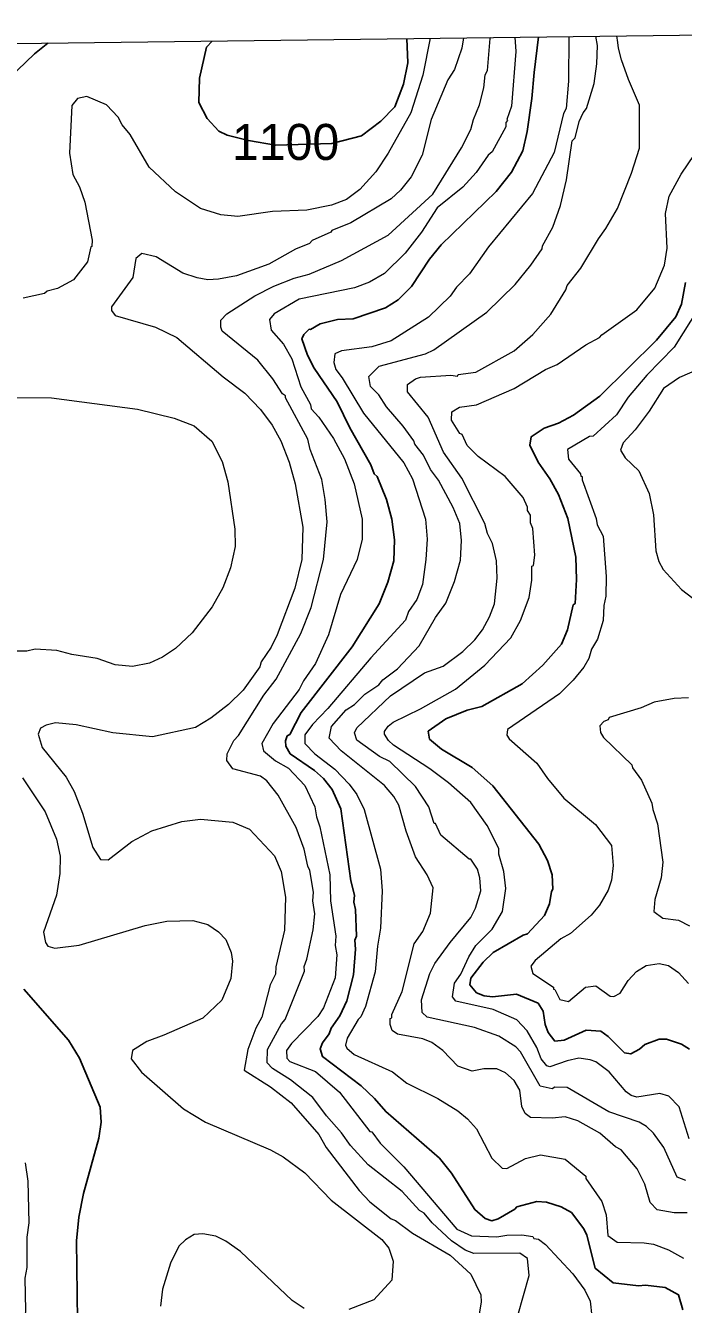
# Model space of a CAD drawing. Extents: x 265.7 to 292.1, y 7676.2 to 7704.2.
# Drawn here: x 288.593 to 290.054, y 7701.364 to 7704.203 of the extents above; entities that cross this region are included whole.
import ezdxf
from ezdxf.enums import TextEntityAlignment as Align

# ---------------------------------------------------------------- set-up
doc = ezdxf.new("R2010")
doc.units = 0
doc.header["$LTSCALE"] = 0.032
for name, color, linetype, lineweight in [('1', 7, 'Continuous', 25), ('2', 7, 'Continuous', 13), ('63', 7, 'Continuous', 25)]:
    doc.layers.add(name, color=color, linetype=linetype, lineweight=lineweight)
doc.layers.add('61', color=7, linetype='Continuous')

msp = doc.modelspace()

# ---------------------------------------------------------------- linework, layer by layer
at = {"layer": '1'}
for points in [[(288.6424, 7704.1641), (288.6129, 7704.1406), (288.5565, 7704.0866)], [(289.4399, 7704.1741), (289.4423, 7704.1205), (289.4325, 7704.0726), (289.4129, 7704.0224), (289.3823, 7703.9905), (289.3394, 7703.9586), (289.2733, 7703.9415), (289.1483, 7703.9378), (289.0883, 7703.9476), (289.0405, 7703.9599), (289.0222, 7703.9684), (288.9964, 7703.9966), (288.978, 7704.0322), (288.9793, 7704.0862), (288.9952, 7704.1548), (289.0076, 7704.1687)], [(289.293, 7702.4643), (289.2739, 7702.5074), (289.2547, 7702.5313), (289.2348, 7702.5497), (289.1805, 7702.5864), (289.171, 7702.6032), (289.1702, 7702.6151), (289.1741, 7702.6263), (289.1797, 7702.6295), (289.2053, 7702.6782), (289.3186, 7702.8242), (289.3784, 7702.9192), (289.3976, 7702.9671), (289.4111, 7703.0149), (289.4127, 7703.0612), (289.4064, 7703.1075), (289.3944, 7703.1506), (289.3736, 7703.2017), (289.3673, 7703.208), (289.3601, 7703.228), (289.313, 7703.3102), (289.2851, 7703.3676), (289.234, 7703.4426), (289.2188, 7703.4714), (289.2069, 7703.5073), (289.2108, 7703.5176), (289.2228, 7703.5288), (289.226, 7703.528), (289.2476, 7703.5408), (289.2859, 7703.5503), (289.3202, 7703.5519), (289.392, 7703.5767), (289.4207, 7703.5942), (289.4502, 7703.6238), (289.4901, 7703.6844), (289.5157, 7703.7163), (289.6378, 7703.8344), (289.6721, 7703.8775), (289.6976, 7703.9246), (289.7072, 7703.9677), (289.7173, 7704.0413), (289.7224, 7704.0986), (289.7319, 7704.1777)], [(290.0583, 7703.6326), (290.0495, 7703.5847), (290.0367, 7703.5567), (289.9944, 7703.5049), (289.8684, 7703.3804), (289.8101, 7703.3381), (289.7766, 7703.3205), (289.7447, 7703.3094), (289.716, 7703.2902), (289.7128, 7703.2719), (289.7311, 7703.2336), (289.7575, 7703.1969), (289.7766, 7703.1618), (289.7974, 7703.1091), (289.8149, 7703.0229), (289.8165, 7702.9734), (289.8133, 7702.92), (289.8093, 7702.9168), (289.7966, 7702.8617), (289.783, 7702.8298), (289.7415, 7702.7835), (289.696, 7702.742), (289.6059, 7702.6917), (289.5739, 7702.683), (289.5261, 7702.6638), (289.4869, 7702.6367)], [(289.4869, 7702.6367), (289.4901, 7702.6191), (289.5165, 7702.5968), (289.5851, 7702.5561), (289.6306, 7702.5154), (289.7327, 7702.3861), (289.7519, 7702.3494)], [(289.3242, 7702.1731), (289.3282, 7702.1819), (289.3258, 7702.2409), (289.3218, 7702.2569), (289.3234, 7702.2728), (289.3154, 7702.3047), (289.293, 7702.4643)], [(289.7519, 7702.3494), (289.7622, 7702.3175), (289.7638, 7702.2856), (289.7606, 7702.2808), (289.7567, 7702.2537), (289.7455, 7702.2273), (289.708, 7702.1866), (289.6984, 7702.1842), (289.6314, 7702.1451), (289.609, 7702.1236), (289.5819, 7702.0885), (289.5795, 7702.0733), (289.5947, 7702.0558), (289.6114, 7702.0494), (289.6298, 7702.047), (289.6832, 7702.0526), (289.7311, 7702.0326), (289.7423, 7702.0151), (289.7471, 7701.9856), (289.7535, 7701.968), (289.7686, 7701.9488), (289.7894, 7701.9504), (289.838, 7701.9728), (289.8708, 7701.9704), (289.8867, 7701.9592), (289.9234, 7701.9225), (289.937, 7701.9201), (289.9562, 7701.9305), (289.9681, 7701.9409), (290, 7701.9528), (290.016, 7701.9528), (290.0495, 7701.9417), (290.0671, 7701.9305)], [(290.0527, 7701.352), (290.0431, 7701.3855), (290.0136, 7701.4014), (289.9697, 7701.407), (289.9538, 7701.4054), (289.8979, 7701.4118), (289.858, 7701.4445), (289.8396, 7701.518), (289.8325, 7701.5323), (289.8053, 7701.5682), (289.7822, 7701.581), (289.7495, 7701.5913), (289.7287, 7701.5929), (289.6841, 7701.581), (289.6793, 7701.5754), (289.6426, 7701.5538), (289.6282, 7701.5499), (289.6138, 7701.5546), (289.5907, 7701.5746), (289.5388, 7701.6552), (289.5125, 7701.6887), (289.3928, 7701.7924), (289.3681, 7701.8212), (289.3385, 7701.8491), (289.2523, 7701.9145), (289.2476, 7701.9313), (289.2523, 7701.9449), (289.2675, 7701.9648), (289.2715, 7701.9776), (289.2906, 7702.0047), (289.3066, 7702.0382), (289.321, 7702.0957), (289.3258, 7702.1531), (289.3242, 7702.1731)], [(288.5892, 7702.0638), (288.6882, 7701.9504), (288.7129, 7701.9105), (288.7584, 7701.802), (288.7608, 7701.7685), (288.756, 7701.7334), (288.7217, 7701.6105), (288.7113, 7701.5579), (288.7065, 7701.5052), (288.7081, 7701.328), (288.7281, 7701.0599), (288.7361, 7701.0232), (288.752, 7700.9083), (288.7504, 7700.7982), (288.7353, 7700.728), (288.7081, 7700.6705), (288.6834, 7700.6322), (288.6044, 7700.5556), (288.5757, 7700.5205)]]:
    msp.add_lwpolyline(points, dxfattribs=at)
at = {"layer": '2'}
for points in [[(289.4914, 7704.1747), (289.4754, 7704.0931), (289.4483, 7704.0091), (289.3984, 7703.9198), (289.3712, 7703.8783), (289.3353, 7703.8392), (289.3058, 7703.8169), (289.2723, 7703.8041), (289.218, 7703.7929), (289.1414, 7703.7905), (289.0648, 7703.7794), (289.0265, 7703.7826), (288.9818, 7703.7969), (288.926, 7703.8336), (288.8677, 7703.8887), (288.8254, 7703.9613), (288.8079, 7703.9828), (288.7991, 7703.9996), (288.7728, 7704.0267), (288.7289, 7704.0459), (288.7081, 7704.0411), (288.6962, 7704.0259), (288.6906, 7703.9198), (288.6978, 7703.8727), (288.7129, 7703.8448), (288.7249, 7703.8113), (288.7409, 7703.7267), (288.7401, 7703.7123), (288.7377, 7703.7115), (288.7305, 7703.6788), (288.6994, 7703.6389), (288.6643, 7703.619), (288.6411, 7703.6134), (288.6355, 7703.6086), (288.5877, 7703.5982)], [(289.5654, 7704.1756), (289.5617, 7704.1531), (289.5452, 7704.1057), (289.5308, 7704.0826), (289.4941, 7703.9948), (289.4734, 7703.915), (289.4494, 7703.8672), (289.4255, 7703.8376), (289.4048, 7703.8185), (289.3154, 7703.765), (289.2731, 7703.7482), (289.2707, 7703.7443), (289.2292, 7703.7259), (289.2236, 7703.7195), (289.1925, 7703.7068), (289.1335, 7703.6732), (289.0616, 7703.6477), (289.0217, 7703.6397), (288.9978, 7703.6389), (288.9739, 7703.6429), (288.942, 7703.6533), (288.8829, 7703.69), (288.851, 7703.6972), (288.8382, 7703.686), (288.831, 7703.6437), (288.7839, 7703.5783), (288.7839, 7703.5703), (288.7919, 7703.5591), (288.8813, 7703.5336), (288.9292, 7703.5105), (289.0321, 7703.4235), (289.08, 7703.3868), (289.1151, 7703.3509), (289.1406, 7703.3158), (289.1598, 7703.2814), (289.1781, 7703.2336), (289.1917, 7703.1857), (289.2085, 7703.0899), (289.2069, 7703.0181), (289.1909, 7702.9543), (289.1518, 7702.8505), (289.1382, 7702.8234), (289.1159, 7702.7907), (289.1135, 7702.7795), (289.076, 7702.7277), (289.0441, 7702.6957), (289.0042, 7702.6654), (288.9707, 7702.6447), (288.8749, 7702.6239), (288.7871, 7702.6327), (288.7058, 7702.651), (288.6595, 7702.655), (288.6387, 7702.6503), (288.626, 7702.6431), (288.6212, 7702.6303), (288.6299, 7702.6008), (288.6834, 7702.5346), (288.701, 7702.5026), (288.7193, 7702.4548), (288.7425, 7702.3782), (288.7592, 7702.3518), (288.7768, 7702.351), (288.8294, 7702.3917), (288.8733, 7702.4157), (288.9404, 7702.4364), (288.9818, 7702.4412), (289.0537, 7702.4348), (289.0904, 7702.4188), (289.1462, 7702.3598), (289.1606, 7702.3255), (289.1702, 7702.268), (289.1678, 7702.1946), (289.1486, 7702.1132), (289.1478, 7702.0973), (289.1366, 7702.0733), (289.1175, 7702.0015), (289.1047, 7701.9776), (289.0864, 7701.9297), (289.0784, 7701.8842), (289.1367, 7701.8475), (289.1829, 7701.8116), (289.2444, 7701.7414), (289.2603, 7701.7127), (289.3337, 7701.6169), (289.3577, 7701.5922), (289.4048, 7701.5539), (289.4143, 7701.5507), (289.4526, 7701.5227), (289.5356, 7701.4733), (289.5819, 7701.431), (289.6043, 7701.3855), (289.6051, 7701.3695), (289.5987, 7701.3344)], [(289.6864, 7701.3392), (289.7112, 7701.4286), (289.708, 7701.4661), (289.6904, 7701.478), (289.5883, 7701.4773), (289.5691, 7701.4844), (289.5388, 7701.5052), (289.4957, 7701.5451), (289.4782, 7701.5666), (289.4678, 7701.573), (289.4295, 7701.6145), (289.3537, 7701.6743), (289.3146, 7701.7166), (289.2947, 7701.7454), (289.2611, 7701.7829), (289.2308, 7701.8236), (289.1813, 7701.8627), (289.1414, 7701.8882), (289.1295, 7701.9002), (289.1303, 7701.9297), (289.1614, 7701.9872), (289.1694, 7701.9967), (289.2125, 7702.1037), (289.2117, 7702.114), (289.218, 7702.1308), (289.2316, 7702.1954), (289.2356, 7702.2313), (289.2308, 7702.2601), (289.2324, 7702.2792), (289.2244, 7702.3271), (289.2196, 7702.3367), (289.2117, 7702.375), (289.1941, 7702.4228), (289.1542, 7702.4947), (289.1287, 7702.5266), (289.1151, 7702.5369), (289.0537, 7702.5529), (289.0401, 7702.5713), (289.0409, 7702.5864), (289.0553, 7702.6159), (289.0656, 7702.6271), (289.1223, 7702.7165), (289.1494, 7702.7524), (289.2045, 7702.8537), (289.2276, 7702.9112), (289.2547, 7703.0181), (289.2627, 7703.1011), (289.2587, 7703.1506), (289.2508, 7703.1953), (289.2252, 7703.2623), (289.2196, 7703.2846), (289.1702, 7703.3764), (289.1702, 7703.3812), (289.1638, 7703.3852), (289.1422, 7703.4187), (289.1087, 7703.4602), (289.0297, 7703.5248), (289.0265, 7703.5336), (289.0265, 7703.5488), (289.0401, 7703.5631), (289.1023, 7703.603), (289.1446, 7703.6246), (289.1893, 7703.6421), (289.2228, 7703.6509), (289.2947, 7703.6812), (289.3984, 7703.7379), (289.4973, 7703.8288), (289.5612, 7703.9318), (289.5819, 7703.9725), (289.5875, 7703.9948), (289.6011, 7704.0267), (289.6106, 7704.065), (289.6138, 7704.0938), (289.6186, 7704.1033), (289.625, 7704.1744), (289.6238, 7704.1764)], [(289.6793, 7704.177), (289.6814, 7704.1458), (289.6722, 7704.0238), (289.6617, 7703.9943), (289.6633, 7703.9924), (289.6593, 7703.9876), (289.6593, 7703.9781), (289.629, 7703.923), (289.6202, 7703.915), (289.5939, 7703.8767), (289.5644, 7703.844), (289.5069, 7703.7985), (289.4726, 7703.7443), (289.4359, 7703.698), (289.3904, 7703.6525), (289.3569, 7703.6333), (289.3234, 7703.6206), (289.2005, 7703.5958), (289.1454, 7703.5631), (289.1351, 7703.5504), (289.1382, 7703.5272), (289.1662, 7703.4961), (289.1845, 7703.4634), (289.2045, 7703.4011), (289.226, 7703.362), (289.2276, 7703.3525), (289.2444, 7703.3341), (289.2771, 7703.2862), (289.301, 7703.2415), (289.3226, 7703.1857), (289.3409, 7703.1075), (289.3409, 7703.0628), (289.3298, 7703.0181), (289.2923, 7702.9399), (289.2659, 7702.8505), (289.2372, 7702.7867), (289.2101, 7702.7484), (289.2005, 7702.7293), (289.143, 7702.6534), (289.1175, 7702.6096), (289.1215, 7702.5928), (289.1478, 7702.5705), (289.1766, 7702.5545), (289.2133, 7702.5162), (289.2356, 7702.4691), (289.2388, 7702.4468), (289.2468, 7702.4244), (289.2691, 7702.3175), (289.2699, 7702.2601), (289.2819, 7702.1819), (289.2803, 7702.1611), (289.2843, 7702.1404), (289.2803, 7702.0893), (289.2547, 7702.0223), (289.242, 7702.0031), (289.1837, 7701.9433), (289.1726, 7701.9281), (289.1734, 7701.9105), (289.1797, 7701.9034), (289.2372, 7701.881), (289.2899, 7701.8355), (289.3577, 7701.7478), (289.3617, 7701.747), (289.3808, 7701.7222), (289.4327, 7701.6696), (289.5508, 7701.5315), (289.5835, 7701.5163), (289.6394, 7701.514), (289.6617, 7701.5179), (289.6952, 7701.5187), (289.7192, 7701.5148), (289.7216, 7701.5108), (289.7319, 7701.5092), (289.7479, 7701.4972), (289.8085, 7701.4318), (289.8349, 7701.3959), (289.8468, 7701.3711), (289.8508, 7701.3376)], [(289.7998, 7704.1786), (289.799, 7704.0794), (289.7934, 7704.0188), (289.7878, 7704.0076), (289.767, 7703.9214), (289.7184, 7703.8304), (289.621, 7703.7115), (289.5787, 7703.6517), (289.55, 7703.6222), (289.5356, 7703.6022), (289.4877, 7703.5559), (289.4048, 7703.5033), (289.3617, 7703.4897), (289.2947, 7703.4809), (289.2795, 7703.4746), (289.2779, 7703.4554), (289.2819, 7703.4394), (289.2962, 7703.4211), (289.3433, 7703.3429), (289.4327, 7703.232), (289.4526, 7703.1969), (289.4814, 7703.1075), (289.4846, 7703.0628), (289.4822, 7703.0181), (289.4742, 7702.9623), (289.4622, 7702.9287), (289.4431, 7702.9024), (289.4367, 7702.8833), (289.3601, 7702.7995), (289.2643, 7702.687), (289.23, 7702.6518), (289.2133, 7702.6287), (289.2133, 7702.6096), (289.2356, 7702.5864), (289.2795, 7702.5521), (289.3114, 7702.5194), (289.329, 7702.4963), (289.3449, 7702.4627), (289.3816, 7702.3303), (289.3848, 7702.2824), (289.3816, 7702.1994), (289.3744, 7702.1595), (289.3697, 7702.1021), (289.3481, 7702.0255), (289.3377, 7702.0023), (289.3313, 7701.9967), (289.3074, 7701.9552), (289.3034, 7701.9393), (289.3066, 7701.9329), (289.3226, 7701.9193), (289.408, 7701.8802), (289.4399, 7701.8555), (289.5085, 7701.8212), (289.5532, 7701.794), (289.5747, 7701.7765), (289.5947, 7701.7541), (289.6282, 7701.6887), (289.6513, 7701.6664), (289.6617, 7701.6656), (289.7032, 7701.6879), (289.7367, 7701.6959), (289.791, 7701.6863), (289.8373, 7701.6488), (289.8373, 7701.644), (289.8724, 7701.593), (289.8827, 7701.5634), (289.8859, 7701.5172), (289.9067, 7701.502), (289.9665, 7701.5012), (289.9873, 7701.498), (290.0208, 7701.4852), (290.0543, 7701.4669)], [(289.5923, 7702.2441), (289.6043, 7702.2824), (289.6019, 7702.3111), (289.5963, 7702.3303), (289.5819, 7702.3526), (289.5779, 7702.3526), (289.5149, 7702.4061), (289.5037, 7702.4316), (289.5005, 7702.4316), (289.4885, 7702.4691), (289.459, 7702.5138), (289.4016, 7702.5697), (289.3792, 7702.5808), (289.329, 7702.6167), (289.3234, 7702.6327), (289.3289, 7702.6439), (289.4032, 7702.7149), (289.479, 7702.766), (289.5205, 7702.7811), (289.5644, 7702.8138), (289.5907, 7702.8394), (289.6074, 7702.8617), (289.6234, 7702.8904), (289.6346, 7702.9192), (289.6402, 7702.9766), (289.6386, 7703.0149), (289.6298, 7703.0532), (289.6186, 7703.0756), (289.613, 7703.0979), (289.562, 7703.1985), (289.5213, 7703.2559), (289.487, 7703.3341), (289.4415, 7703.39), (289.4415, 7703.4059), (289.459, 7703.4187), (289.4702, 7703.4227), (289.5372, 7703.4267), (289.5524, 7703.4251), (289.554, 7703.4283), (289.5931, 7703.4339), (289.6777, 7703.4809), (289.7192, 7703.5176), (289.7591, 7703.5623), (289.7926, 7703.6166), (289.7958, 7703.6262), (289.8261, 7703.6645), (289.8652, 7703.7299), (289.8819, 7703.7522), (289.9075, 7703.7969), (289.9386, 7703.8751), (289.9562, 7703.931), (289.9561, 7704.0263), (289.9321, 7704.0836), (289.9167, 7704.1267), (289.9099, 7704.1525), (289.9082, 7704.1657), (289.906, 7704.1799)], [(289.4925, 7703.2176), (289.4766, 7703.2495), (289.4574, 7703.2735), (289.455, 7703.2814), (289.4319, 7703.3134), (289.3944, 7703.3565), (289.3776, 7703.3836), (289.3593, 7703.4019), (289.3553, 7703.4243), (289.3784, 7703.4466), (289.4814, 7703.4745), (289.4997, 7703.4833), (289.617, 7703.5671), (289.6801, 7703.6286), (289.7152, 7703.6709), (289.7399, 7703.7076), (289.7407, 7703.7139), (289.7638, 7703.7554), (289.7806, 7703.8033), (289.7942, 7703.8608), (289.8069, 7703.9469), (289.8133, 7703.9541), (289.8221, 7703.99), (289.8309, 7704.0092), (289.8389, 7704.0188), (289.8556, 7704.0746), (289.8619, 7704.1184), (289.8628, 7704.1591), (289.8593, 7704.1793)], [(289.7503, 7701.8938), (289.7383, 7701.909), (289.7287, 7701.9345), (289.7072, 7701.9712), (289.684, 7701.9959), (289.6314, 7702.0191), (289.5484, 7702.0374), (289.5412, 7702.047), (289.5452, 7702.0773), (289.5596, 7702.0973), (289.5771, 7702.1356), (289.5931, 7702.1611), (289.629, 7702.197), (289.6521, 7702.2361), (289.6593, 7702.2872), (289.6553, 7702.3255), (289.6441, 7702.3638), (289.6442, 7702.3766), (289.6178, 7702.4276), (289.5819, 7702.4787), (289.5324, 7702.5218), (289.4909, 7702.5529), (289.4103, 7702.6056), (289.3992, 7702.6159), (289.3904, 7702.6303), (289.3904, 7702.6359), (289.3984, 7702.6479), (289.4095, 7702.6566), (289.4702, 7702.6862), (289.5476, 7702.73), (289.613, 7702.7835), (289.6705, 7702.8442), (289.692, 7702.8825), (289.7112, 7702.9335), (289.7176, 7702.9718), (289.7176, 7703.0029), (289.7208, 7703.0045), (289.7239, 7703.0277), (289.7192, 7703.0867), (289.7144, 7703.0995), (289.7144, 7703.1163), (289.708, 7703.1266), (289.708, 7703.1338), (289.6984, 7703.1554), (289.6577, 7703.2017), (289.5979, 7703.2463), (289.5739, 7703.2711), (289.5628, 7703.295), (289.5572, 7703.2974), (289.5388, 7703.3269), (289.5396, 7703.3453), (289.5564, 7703.3557), (289.5947, 7703.3612), (289.6777, 7703.3971), (289.7479, 7703.4394), (289.7734, 7703.4506), (289.8373, 7703.4945), (289.8676, 7703.5105), (289.8724, 7703.5168), (289.9506, 7703.5719), (289.9905, 7703.6198), (290.012, 7703.6709), (290.0176, 7703.7092), (290.0144, 7703.7858), (290.0224, 7703.8241), (290.0487, 7703.8735), (290.0926, 7703.9374)], [(290.0894, 7703.5783), (290.0336, 7703.4889), (289.9729, 7703.4267), (289.9314, 7703.378), (289.9051, 7703.3389), (289.8532, 7703.2918), (289.8452, 7703.291), (289.7966, 7703.2623), (289.799, 7703.2407), (289.8253, 7703.208), (289.8261, 7703.2024), (289.8293, 7703.2017), (289.8293, 7703.1945), (289.8604, 7703.1091), (289.862, 7703.0947), (289.8756, 7703.0692), (289.8827, 7702.9798), (289.8819, 7702.9367), (289.8772, 7702.916), (289.8756, 7702.8825), (289.8628, 7702.841), (289.85, 7702.8186), (289.8436, 7702.7979), (289.8325, 7702.7787), (289.8093, 7702.75), (289.779, 7702.7197), (289.6633, 7702.6407), (289.6617, 7702.6279), (289.6673, 7702.6199)], [(290.0846, 7703.4386), (290.0455, 7703.4219), (290.0096, 7703.3971), (289.9777, 7703.3469), (289.9466, 7703.3054), (289.9202, 7703.2767), (289.9139, 7703.2607), (289.9242, 7703.2431), (289.9546, 7703.2144), (289.9777, 7703.1641), (289.9873, 7703.1171), (289.9929, 7703.0373), (289.9992, 7703.0133), (290.0088, 7702.9958), (290.0495, 7702.9511), (290.1158, 7702.9008)], [(288.5669, 7703.3772), (288.6507, 7703.3764), (288.8414, 7703.3517), (288.9228, 7703.3317), (288.9675, 7703.3142), (289.0066, 7703.2806), (289.0297, 7703.2352), (289.0425, 7703.1905), (289.0576, 7703.0851), (289.0584, 7703.0468), (289.0481, 7702.999), (289.0313, 7702.9551), (289.0074, 7702.9128), (288.9627, 7702.8553), (288.926, 7702.8202), (288.8973, 7702.8011), (288.8685, 7702.7875), (288.8302, 7702.7803), (288.7919, 7702.7843), (288.752, 7702.7979), (288.6962, 7702.8067), (288.6627, 7702.8154), (288.6148, 7702.8186), (288.5956, 7702.8146), (288.5637, 7702.8146)], [(289.5452, 7702.9686), (289.5588, 7703.0165), (289.5612, 7703.0596), (289.5572, 7703.0979), (289.5428, 7703.133), (289.5101, 7703.1937), (289.4925, 7703.2176)], [(290.0623, 7701.5674), (290.0336, 7701.5674), (289.9953, 7701.5738), (289.9801, 7701.5906), (289.9681, 7701.6313), (289.9514, 7701.6648), (289.9155, 7701.7071), (289.9027, 7701.7142), (289.8684, 7701.7446), (289.8197, 7701.7717), (289.791, 7701.7805), (289.7623, 7701.7773), (289.7144, 7701.7789), (289.7024, 7701.7877), (289.6952, 7701.8036), (289.6904, 7701.8395), (289.6777, 7701.8611), (289.6585, 7701.8786), (289.6394, 7701.8874), (289.6106, 7701.8874), (289.5851, 7701.8818), (289.5532, 7701.893), (289.5197, 7701.9281), (289.4949, 7701.9457), (289.475, 7701.9536), (289.4191, 7701.964), (289.4072, 7701.972), (289.4024, 7701.9856), (289.4024, 7701.9991), (289.4064, 7702.0007), (289.4064, 7702.0079), (289.4295, 7702.059), (289.4558, 7702.1643), (289.475, 7702.1922), (289.4925, 7702.2329), (289.4981, 7702.2888), (289.4846, 7702.3175), (289.459, 7702.3574), (289.4383, 7702.4149), (289.4223, 7702.4723), (289.4111, 7702.4915), (289.3904, 7702.5162), (289.2938, 7702.5928), (289.2675, 7702.6215), (289.2723, 7702.6471), (289.305, 7702.6838), (289.3234, 7702.6957), (289.3465, 7702.7189), (289.3776, 7702.7396), (289.3864, 7702.7508), (289.4191, 7702.7747), (289.467, 7702.8258), (289.5037, 7702.8889), (289.5261, 7702.9208), (289.5452, 7702.9686)], [(290.0655, 7702.7109), (290.0336, 7702.7093), (289.9889, 7702.7013), (289.9602, 7702.6886), (289.8891, 7702.667), (289.8867, 7702.6622), (289.8772, 7702.6582)], [(289.8772, 7702.6582), (289.8684, 7702.6487), (289.87, 7702.6335), (289.8764, 7702.6223), (289.9394, 7702.5617), (289.941, 7702.5553), (289.9609, 7702.5282)], [(289.6673, 7702.6199), (289.7287, 7702.5657), (289.7519, 7702.5314), (289.7886, 7702.4883), (289.8588, 7702.4292), (289.8939, 7702.3829), (289.8979, 7702.3383)], [(288.5861, 7702.533), (288.6363, 7702.4579), (288.6619, 7702.3973), (288.6698, 7702.359), (288.669, 7702.3207), (288.6619, 7702.2728), (288.6331, 7702.1906), (288.6371, 7702.1675), (288.6427, 7702.1595), (288.6579, 7702.1547)], [(289.9609, 7702.5282), (289.9841, 7702.4771), (289.9857, 7702.4627), (289.9961, 7702.4308), (290.008, 7702.3462), (290.0048, 7702.3111), (289.9905, 7702.2632), (289.9881, 7702.2361), (290.008, 7702.2217), (290.0431, 7702.217), (290.0671, 7702.2042)], [(289.8979, 7702.3383), (289.8939, 7702.3063), (289.8867, 7702.284), (289.8676, 7702.2505), (289.8492, 7702.2281), (289.803, 7702.1874), (289.7814, 7702.1755), (289.7247, 7702.1276), (289.7152, 7702.1148), (289.7192, 7702.0989), (289.7654, 7702.0685), (289.7654, 7702.0637), (289.7686, 7702.063), (289.7798, 7702.0414), (289.799, 7702.0366), (289.8365, 7702.0685), (289.8596, 7702.0717), (289.8915, 7702.0486), (289.8995, 7702.0478), (289.9131, 7702.055), (289.9314, 7702.0829), (289.9498, 7702.1029), (289.9713, 7702.1164), (290, 7702.1212), (290.0208, 7702.1164), (290.0431, 7702.1013), (290.0655, 7702.0765)], [(289.4734, 7702.0119), (289.4726, 7702.0406), (289.4909, 7702.0989), (289.5021, 7702.1212), (289.5356, 7702.1675), (289.5819, 7702.2234), (289.5923, 7702.2441)], [(288.6579, 7702.1547), (288.7121, 7702.1619), (288.859, 7702.205), (288.9068, 7702.2146), (288.9643, 7702.2162), (288.9978, 7702.2074), (289.0217, 7702.1914)], [(289.0217, 7702.1914), (289.0377, 7702.1739), (289.0497, 7702.1452), (289.0529, 7702.126), (289.0489, 7702.0877), (289.0289, 7702.0398), (288.9866, 7701.9999), (288.9005, 7701.9616), (288.8622, 7701.948), (288.8302, 7701.9281), (288.8278, 7701.909), (288.8502, 7701.8794), (288.9435, 7701.798), (288.993, 7701.7685), (289.1367, 7701.7071), (289.1654, 7701.6919), (289.2133, 7701.656), (289.2715, 7701.5953), (289.384, 7701.5084), (289.4, 7701.4892), (289.4096, 7701.4605), (289.4064, 7701.4182), (289.3665, 7701.3743), (289.3106, 7701.3528)], [(290.0591, 7701.6392), (290.0399, 7701.6464), (290.0104, 7701.7127), (289.9873, 7701.7446), (289.9721, 7701.7589), (289.9554, 7701.7685), (289.8883, 7701.7916), (289.7958, 7701.8459), (289.7686, 7701.8467), (289.7623, 7701.8427), (289.7359, 7701.8483), (289.692, 7701.9249), (289.6817, 7701.9361), (289.6442, 7701.96), (289.5899, 7701.9792), (289.4846, 7702.0015), (289.4734, 7702.0119)], [(289.8891, 7701.8802), (289.8596, 7701.9026), (289.8468, 7701.9073), (289.8213, 7701.9105), (289.7958, 7701.905), (289.7575, 7701.8914), (289.7503, 7701.8938)], [(290.0663, 7701.7318), (290.0447, 7701.8028), (290.0216, 7701.8268), (290.0016, 7701.8323), (289.9506, 7701.8244), (289.9378, 7701.8283), (289.9266, 7701.8363), (289.8891, 7701.8802)], [(288.5924, 7701.6783), (288.598, 7701.6376), (288.6004, 7701.5451), (288.5956, 7701.5132), (288.5956, 7701.4461), (288.5916, 7701.4222), (288.5932, 7701.3504), (288.5908, 7701.3232), (288.598, 7701.2674), (288.5988, 7701.2355), (288.6028, 7701.2195), (288.6108, 7701.0073), (288.614, 7700.9881), (288.6116, 7700.961), (288.6132, 7700.9067), (288.6084, 7700.8748), (288.61, 7700.8189), (288.5916, 7700.7024)], [(289.2117, 7701.3552), (289.1853, 7701.3727), (289.0704, 7701.482), (289.0377, 7701.5044), (289.0154, 7701.5156), (288.9866, 7701.5211), (288.9675, 7701.5195), (288.9483, 7701.5076), (288.9332, 7701.4932), (288.9148, 7701.4557), (288.8973, 7701.3983), (288.8925, 7701.36)]]:
    msp.add_lwpolyline(points, dxfattribs=at)
at = {"layer": '63', "lineweight": 13}
msp.add_lwpolyline([(285.9123, 7704.1296), (286.4437, 7704.1364), (286.9751, 7704.1431), (287.5065, 7704.1498), (288.0379, 7704.1565), (288.5693, 7704.1632), (289.1007, 7704.1699), (289.6321, 7704.1765), (290.1635, 7704.1832), (290.6949, 7704.1898), (291.2263, 7704.1964), (291.7577, 7704.203)], dxfattribs=at)

# ---------------------------------------------------------------- texts
at = {"layer": '61'}
msp.add_text('1100', height=0.08, dxfattribs=at).set_placement((289.1706, 7703.9047), align=Align.CENTER)

doc.saveas('drawing.dxf')
